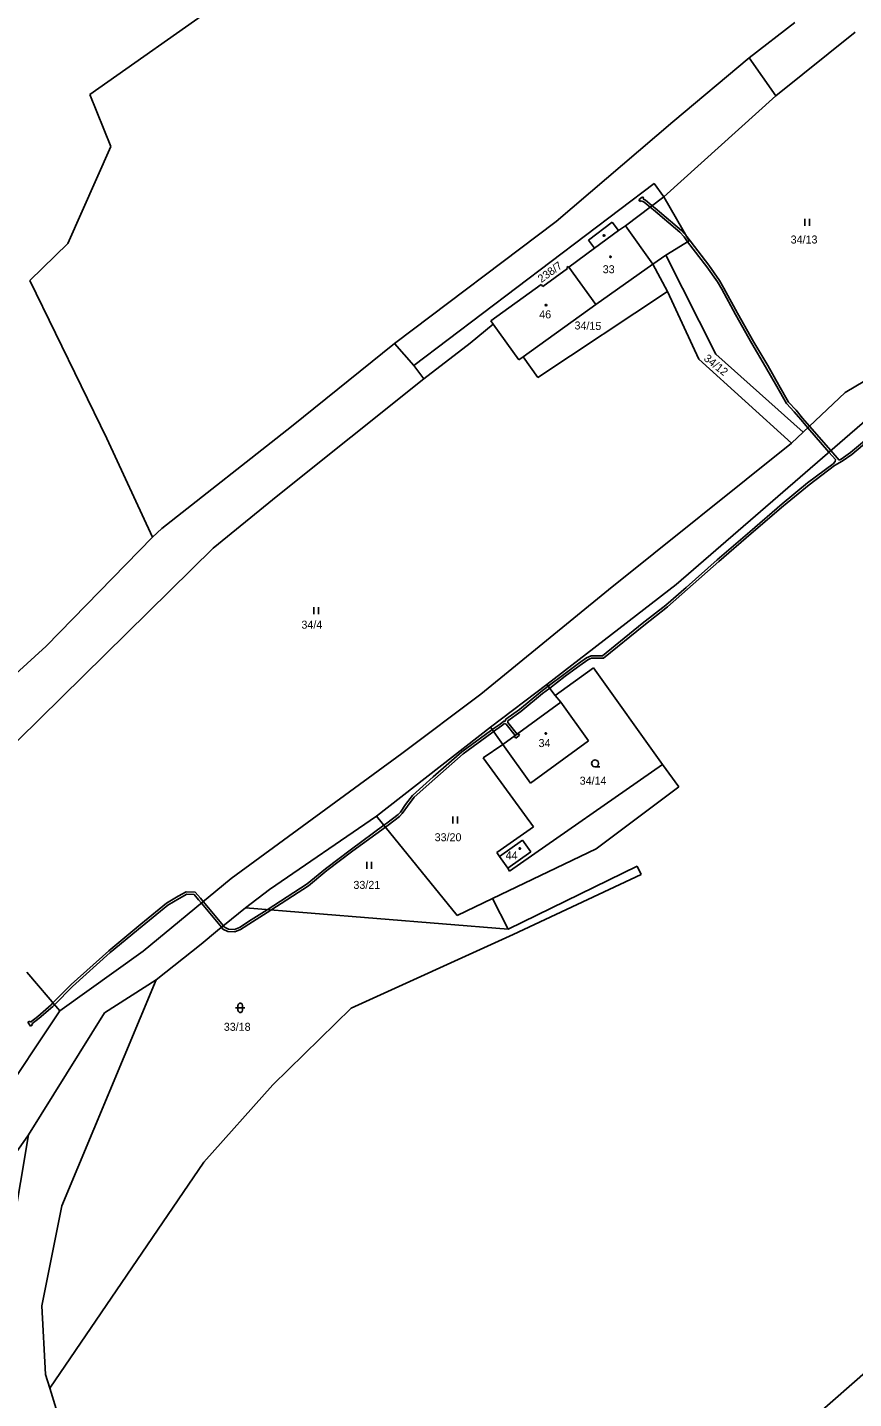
# Model space of a CAD drawing. Extents: x -811039 to -805820, y -1161436 to -1155864.
# Drawn here: x -810537.2 to -810361.7, y -1161047.6 to -1160756.4 of the extents above; entities that cross this region are included whole.
import ezdxf

# ---------------------------------------------------------------- set-up
doc = ezdxf.new("R2010")
doc.units = 0
for name, color, linetype in [('Default', 7, 'Continuous'), ('Hranice parcel', 7, 'Continuous'), ('Parcelní čísla', 7, 'Continuous'), ('Vnitřní kresba', 7, 'Continuous'), ('Věcná břemena k části', 7, 'Continuous'), ('Značky budov', 7, 'Continuous'), ('Značky kultur', 7, 'Continuous')]:
    doc.layers.add(name, color=color, linetype=linetype)

# ---------------------------------------------------------------- blocks, each defined once
blk = doc.blocks.new('304')
at = {"layer": 'Default'}
blk.add_lwpolyline([(0, 0), (-0.38, 0.1), (-0.65, 0.37), (-0.75, 0.74), (-0.65, 1.11), (-0.38, 1.38), (-0.01, 1.48), (0.36, 1.38), (0.63, 1.11), (0.73, 0.73), (0.63, 0.35), (0.36, 0.08), (-0.02, -0.02), (0.98, -0.02)], dxfattribs=at)
blk = doc.blocks.new('306')
at = {"layer": 'Default'}
for p, q in [((-0.5, 1.5), (-0.5, 0)), ((0.5, 0), (0.5, 1.5))]:
    blk.add_line(p, q, dxfattribs=at)
blk = doc.blocks.new('316')
at = {"layer": 'Default'}
for points in [[(-1, 1), (0.27, 1), (1, 1)], [(-0.5, 1.5), (-0.4, 1.79), (-0.15, 1.97), (0.16, 1.97), (0.41, 1.79), (0.51, 1.5), (0.51, 0.5), (0.41, 0.21), (0.16, 0.03), (-0.15, 0.03), (-0.4, 0.21), (-0.5, 0.5), (-0.5, 1.5)]]:
    blk.add_lwpolyline(points, dxfattribs=at)
blk = doc.blocks.new('402')
at = {"layer": 'Default'}
blk.add_lwpolyline([(0.09, 0.15), (0.18, 0), (0.09, -0.15), (-0.09, -0.15), (-0.18, 0), (-0.09, 0.15), (0.09, 0.15)], dxfattribs=at)

msp = doc.modelspace()

# ---------------------------------------------------------------- linework, layer by layer
at = {"layer": 'Hranice parcel'}
for p, q in [((-810495.95, -1160750.93), (-810523.97, -1160770.58)), ((-810383.89, -1160762.81), (-810374.25, -1160755.33)), ((-810361.37, -1160757.38), (-810378.26, -1160770.87)), ((-810400.09, -1160776.41), (-810383.89, -1160762.81)), ((-810523.97, -1160770.58), (-810519.48, -1160781.67)), ((-810378.26, -1160770.87), (-810402.06, -1160792.32)), ((-810400.09, -1160776.41), (-810424.9, -1160797.56)), ((-810519.48, -1160781.67), (-810528.63, -1160802.23)), ((-810404.12, -1160789.52), (-810455.16, -1160828.19)), ((-810402.06, -1160792.32), (-810404.12, -1160789.52)), ((-810402.06, -1160792.32), (-810410.16, -1160798.46)), ((-810402.06, -1160792.32), (-810396.64, -1160801.67)), ((-810424.9, -1160797.56), (-810459.25, -1160823.48)), ((-810413.01, -1160797.73), (-810418.01, -1160801.55)), ((-810411.63, -1160799.49), (-810413.01, -1160797.73)), ((-810410.16, -1160798.46), (-810411.63, -1160799.49)), ((-810528.63, -1160802.23), (-810536.67, -1160810.12)), ((-810416.75, -1160803.27), (-810422.24, -1160807.27)), ((-810418.01, -1160801.55), (-810416.75, -1160803.27)), ((-810396.64, -1160801.67), (-810401.59, -1160804.69)), ((-810401.59, -1160804.69), (-810404.35, -1160806.62)), ((-810401.59, -1160804.69), (-810391.01, -1160825.74)), ((-810422.5, -1160807.55), (-810427.75, -1160811.4)), ((-810422.35, -1160807.12), (-810422.66, -1160807.34)), ((-810422.5, -1160807.55), (-810422.66, -1160807.34)), ((-810422.24, -1160807.27), (-810422.35, -1160807.12)), ((-810422.24, -1160807.27), (-810416.48, -1160815.21)), ((-810416.48, -1160815.21), (-810404.35, -1160806.62)), ((-810404.35, -1160806.62), (-810401.26, -1160812.41)), ((-810536.67, -1160810.12), (-810520.32, -1160843.66)), ((-810428.1, -1160810.94), (-810438.78, -1160818.67)), ((-810428.1, -1160810.94), (-810427.75, -1160811.4)), ((-810428.81, -1160830.74), (-810401.26, -1160812.41)), ((-810401.26, -1160812.41), (-810394.63, -1160826.8)), ((-810416.48, -1160815.21), (-810431.93, -1160826.31)), ((-810363.54, -1160833.87), (-810331.75, -1160815.16)), ((-810438.26, -1160819.39), (-810443.14, -1160823.4)), ((-810438.78, -1160818.67), (-810438.26, -1160819.39)), ((-810438.26, -1160819.39), (-810432.81, -1160826.94)), ((-810459.25, -1160823.48), (-810481.1, -1160841.14)), ((-810443.14, -1160823.4), (-810453.03, -1160830.99)), ((-810432.81, -1160826.94), (-810431.93, -1160826.31)), ((-810428.81, -1160830.74), (-810431.93, -1160826.31)), ((-810391.01, -1160825.74), (-810372.47, -1160842.32)), ((-810455.16, -1160828.19), (-810453.03, -1160830.99)), ((-810394.63, -1160826.8), (-810374.94, -1160844.63)), ((-810453.03, -1160830.99), (-810484, -1160855.74)), ((-810372.47, -1160842.32), (-810363.54, -1160833.87)), ((-810399.4, -1160874.7), (-810354.5, -1160835.77)), ((-810508.66, -1160862.79), (-810481.1, -1160841.14)), ((-810520.32, -1160843.66), (-810510.6, -1160864.59)), ((-810374.94, -1160844.63), (-810372.47, -1160842.32)), ((-810413.8, -1160875.77), (-810374.94, -1160844.63)), ((-810484, -1160855.74), (-810497.78, -1160866.95)), ((-810510.6, -1160864.59), (-810508.66, -1160862.79)), ((-810497.78, -1160866.95), (-810545.34, -1160913.8)), ((-810510.6, -1160864.59), (-810533.18, -1160887.75)), ((-810440.91, -1160897.93), (-810413.8, -1160875.77)), ((-810426.88, -1160895.88), (-810399.4, -1160874.7)), ((-810533.18, -1160887.75), (-810595.17, -1160944.17)), ((-810417, -1160892.37), (-810425.11, -1160898.24)), ((-810402.3, -1160912.87), (-810417, -1160892.37)), ((-810438.86, -1160904.96), (-810426.88, -1160895.88)), ((-810425.11, -1160898.24), (-810426.88, -1160895.88)), ((-810457.71, -1160910.59), (-810440.91, -1160897.93)), ((-810425.11, -1160898.24), (-810423.94, -1160899.66)), ((-810423.94, -1160899.66), (-810418.05, -1160907.88)), ((-810463.04, -1160923.9), (-810438.86, -1160904.96)), ((-810438.86, -1160904.96), (-810436.22, -1160908.66)), ((-810418.05, -1160907.88), (-810430.37, -1160916.87)), ((-810493.91, -1160937.11), (-810457.71, -1160910.59)), ((-810436.22, -1160908.66), (-810440.39, -1160911.48)), ((-810430.37, -1160916.87), (-810436.22, -1160908.66)), ((-810440.39, -1160911.48), (-810429.7, -1160926.15)), ((-810434.81, -1160935.56), (-810402.3, -1160912.87)), ((-810402.3, -1160912.87), (-810398.85, -1160917.65)), ((-810398.85, -1160917.65), (-810416.39, -1160930.82)), ((-810463.04, -1160923.9), (-810485.8, -1160939.44)), ((-810445.93, -1160944.94), (-810463.04, -1160923.9)), ((-810429.7, -1160926.15), (-810437.53, -1160931.57)), ((-810438.42, -1160941.35), (-810416.39, -1160930.82)), ((-810436.91, -1160932.46), (-810432.02, -1160928.98)), ((-810430.29, -1160931.42), (-810435.18, -1160934.91)), ((-810432.02, -1160928.98), (-810430.29, -1160931.42)), ((-810437.53, -1160931.57), (-810436.91, -1160932.46)), ((-810435.18, -1160934.91), (-810436.91, -1160932.46)), ((-810512.63, -1160952.57), (-810493.91, -1160937.11)), ((-810435.18, -1160934.91), (-810434.81, -1160935.56)), ((-810407.69, -1160934.51), (-810435.08, -1160947.9)), ((-810406.87, -1160936.24), (-810434.06, -1160948.99)), ((-810407.69, -1160934.51), (-810406.87, -1160936.24)), ((-810485.8, -1160939.44), (-810490.9, -1160943.37)), ((-810445.93, -1160944.94), (-810438.42, -1160941.35)), ((-810435.08, -1160947.9), (-810438.42, -1160941.35)), ((-810490.9, -1160943.37), (-810496.84, -1160948.18)), ((-810435.08, -1160947.9), (-810490.9, -1160943.37)), ((-810496.84, -1160948.18), (-810500.32, -1160951.09)), ((-810500.32, -1160951.09), (-810509.82, -1160958.61)), ((-810434.06, -1160948.99), (-810468.42, -1160964.68)), ((-810530.31, -1160965.25), (-810512.63, -1160952.57)), ((-810530.31, -1160965.25), (-810537.29, -1160957)), ((-810529.92, -1161006.64), (-810509.82, -1160958.61)), ((-810509.82, -1160958.61), (-810520.81, -1160965.65)), ((-810549.36, -1160993.72), (-810530.31, -1160965.25)), ((-810520.81, -1160965.65), (-810536.99, -1160991.57)), ((-810485.1, -1160980.96), (-810468.42, -1160964.68)), ((-810499.76, -1160997.38), (-810485.1, -1160980.96)), ((-810536.99, -1160991.57), (-810560.62, -1161025.39)), ((-810536.99, -1160991.57), (-810544.89, -1161038.54)), ((-810499.76, -1160997.38), (-810532.44, -1161045.37)), ((-810534.14, -1161027.86), (-810529.92, -1161006.64)), ((-810533.34, -1161042.48), (-810534.14, -1161027.86)), ((-810376.47, -1161057.05), (-810353.34, -1161036.78)), ((-810533.34, -1161042.48), (-810532.44, -1161045.37)), ((-810532.44, -1161045.37), (-810531.08, -1161049.77))]:
    msp.add_line(p, q, dxfattribs=at)
at = {"layer": 'Vnitřní kresba'}
for p, q in [((-810416.75, -1160803.27), (-810411.63, -1160799.49)), ((-810404.35, -1160806.62), (-810410.16, -1160798.46)), ((-810436.22, -1160908.66), (-810423.94, -1160899.66))]:
    msp.add_line(p, q, dxfattribs=at)
at = {"layer": 'Věcná břemena k části'}
for p, q in [((-810407.34, -1160792.94), (-810406.57, -1160792.31)), ((-810407.03, -1160793.33), (-810407.34, -1160792.94)), ((-810406.86, -1160793.19), (-810407.03, -1160793.33)), ((-810406.22, -1160793.46), (-810406.86, -1160793.19)), ((-810406.57, -1160792.31), (-810406.25, -1160792.7)), ((-810406.25, -1160792.7), (-810406.42, -1160792.83)), ((-810406.42, -1160792.83), (-810405.96, -1160793.04)), ((-810404.96, -1160794.52), (-810406.22, -1160793.46)), ((-810405.96, -1160793.04), (-810404.55, -1160794.21)), ((-810404.22, -1160795.13), (-810404.96, -1160794.52)), ((-810404.55, -1160794.21), (-810403.9, -1160794.75)), ((-810398.66, -1160799.87), (-810404.22, -1160795.13)), ((-810403.9, -1160794.75), (-810398.32, -1160799.51)), ((-810397.75, -1160800.86), (-810398.66, -1160799.87)), ((-810398.32, -1160799.51), (-810397.17, -1160800.75)), ((-810396.98, -1160801.87), (-810397.75, -1160800.86)), ((-810397.17, -1160800.75), (-810392.51, -1160806.88)), ((-810392.91, -1160807.18), (-810396.98, -1160801.87)), ((-810390.66, -1160810.37), (-810392.91, -1160807.18)), ((-810392.51, -1160806.88), (-810390.24, -1160810.09)), ((-810389.7, -1160811.94), (-810390.66, -1160810.37)), ((-810390.24, -1160810.09), (-810389.26, -1160811.7)), ((-810386.8, -1160817.31), (-810389.7, -1160811.94)), ((-810389.26, -1160811.7), (-810386.36, -1160817.07)), ((-810383.37, -1160823.49), (-810386.8, -1160817.31)), ((-810386.36, -1160817.07), (-810382.93, -1160823.23)), ((-810380.42, -1160828.41), (-810383.37, -1160823.49)), ((-810382.93, -1160823.23), (-810379.98, -1160828.15)), ((-810378.04, -1160832.59), (-810380.42, -1160828.41)), ((-810379.98, -1160828.15), (-810377.6, -1160832.35)), ((-810377.6, -1160832.35), (-810375.58, -1160835.96)), ((-810375.98, -1160836.26), (-810378.04, -1160832.59)), ((-810374.34, -1160837.98), (-810375.98, -1160836.26)), ((-810375.58, -1160835.96), (-810373.96, -1160837.64)), ((-810372.96, -1160839.65), (-810374.34, -1160837.98)), ((-810373.96, -1160837.64), (-810372.58, -1160839.33)), ((-810371.47, -1160841.37), (-810372.96, -1160839.65)), ((-810372.58, -1160839.33), (-810371.1, -1160841.03)), ((-810371.1, -1160841.03), (-810371.47, -1160841.37)), ((-810371.47, -1160841.37), (-810371.1, -1160841.03)), ((-810371.1, -1160841.03), (-810366.58, -1160846.24)), ((-810366.96, -1160846.57), (-810371.47, -1160841.37)), ((-810362.41, -1160846.66), (-810356.12, -1160841.37)), ((-810355.8, -1160841.75), (-810362.11, -1160847.06)), ((-810366.96, -1160846.57), (-810366.58, -1160846.24)), ((-810366.58, -1160846.24), (-810366.96, -1160846.57)), ((-810365.6, -1160848.13), (-810366.96, -1160846.57)), ((-810366.58, -1160846.24), (-810364.81, -1160848.27)), ((-810364.39, -1160848.03), (-810362.41, -1160846.66)), ((-810371.49, -1160853.07), (-810366.09, -1160849.03)), ((-810365.78, -1160849.42), (-810371.19, -1160853.47)), ((-810366.09, -1160849.03), (-810365.68, -1160848.56)), ((-810364.13, -1160848.45), (-810365.78, -1160849.42)), ((-810365.68, -1160848.56), (-810365.6, -1160848.13)), ((-810364.81, -1160848.27), (-810364.39, -1160848.03)), ((-810362.11, -1160847.06), (-810364.13, -1160848.45)), ((-810376.91, -1160857.56), (-810371.49, -1160853.07)), ((-810371.19, -1160853.47), (-810376.59, -1160857.94)), ((-810383.78, -1160863.45), (-810376.91, -1160857.56)), ((-810376.59, -1160857.94), (-810383.46, -1160863.83)), ((-810390.7, -1160869.43), (-810383.78, -1160863.45)), ((-810383.46, -1160863.83), (-810390.38, -1160869.81)), ((-810397.32, -1160875.28), (-810390.7, -1160869.43)), ((-810390.38, -1160869.81), (-810396.98, -1160875.66)), ((-810401.59, -1160879.03), (-810397.32, -1160875.28)), ((-810396.98, -1160875.66), (-810401.27, -1160879.41)), ((-810406.61, -1160882.98), (-810401.59, -1160879.03)), ((-810401.27, -1160879.41), (-810406.29, -1160883.38)), ((-810415.05, -1160889.79), (-810406.61, -1160882.98)), ((-810406.29, -1160883.38), (-810414.87, -1160890.29)), ((-810420.16, -1160891.47), (-810418.45, -1160890.28)), ((-810418.19, -1160890.7), (-810419.86, -1160891.87)), ((-810418.45, -1160890.28), (-810417.97, -1160890)), ((-810417.77, -1160890.46), (-810418.19, -1160890.7)), ((-810417.97, -1160890), (-810417.45, -1160889.82)), ((-810417.37, -1160890.32), (-810417.77, -1160890.46)), ((-810417.45, -1160889.82), (-810415.05, -1160889.79)), ((-810414.87, -1160890.29), (-810417.37, -1160890.32)), ((-810423.29, -1160893.77), (-810420.16, -1160891.47)), ((-810419.86, -1160891.87), (-810422.99, -1160894.17)), ((-810428.13, -1160897.45), (-810426.58, -1160896.28)), ((-810426.58, -1160896.28), (-810423.29, -1160893.77)), ((-810426.58, -1160896.28), (-810426.28, -1160896.68)), ((-810426.28, -1160896.68), (-810426.58, -1160896.28)), ((-810422.99, -1160894.17), (-810426.28, -1160896.68)), ((-810432.7, -1160901.24), (-810428.13, -1160897.45)), ((-810427.81, -1160897.85), (-810432.4, -1160901.64)), ((-810426.28, -1160896.68), (-810427.81, -1160897.85)), ((-810435.6, -1160903.3), (-810432.7, -1160901.24)), ((-810432.4, -1160901.64), (-810435.16, -1160903.6)), ((-810438.49, -1160905.48), (-810436.83, -1160904.3)), ((-810436.53, -1160904.7), (-810438.2, -1160905.89)), ((-810436.83, -1160904.3), (-810436.03, -1160903.71)), ((-810435.87, -1160904.21), (-810436.53, -1160904.7)), ((-810436.03, -1160903.71), (-810435.72, -1160903.72)), ((-810435.55, -1160904.32), (-810435.87, -1160904.21)), ((-810435.72, -1160903.72), (-810435.6, -1160903.3)), ((-810433.59, -1160906.73), (-810435.55, -1160904.32)), ((-810435.16, -1160903.6), (-810435.16, -1160904.01)), ((-810435.16, -1160904.01), (-810433.19, -1160906.44)), ((-810444.95, -1160910.24), (-810438.85, -1160905.74)), ((-810438.55, -1160906.14), (-810444.63, -1160910.64)), ((-810438.85, -1160905.74), (-810438.49, -1160905.48)), ((-810438.2, -1160905.89), (-810438.55, -1160906.14)), ((-810433.79, -1160906.88), (-810433.59, -1160906.73)), ((-810433.5, -1160907.28), (-810433.79, -1160906.88)), ((-810432.69, -1160906.69), (-810433.5, -1160907.28)), ((-810433.19, -1160906.44), (-810432.98, -1160906.29)), ((-810432.98, -1160906.29), (-810432.69, -1160906.69)), ((-810451.04, -1160915.54), (-810444.95, -1160910.24)), ((-810444.63, -1160910.64), (-810450.7, -1160915.92)), ((-810455.43, -1160919.51), (-810451.04, -1160915.54)), ((-810450.7, -1160915.92), (-810455.05, -1160919.85)), ((-810456.87, -1160921.42), (-810455.43, -1160919.51)), ((-810455.05, -1160919.85), (-810456.47, -1160921.72)), ((-810457.99, -1160923.02), (-810456.87, -1160921.42)), ((-810456.47, -1160921.72), (-810457.59, -1160923.34)), ((-810461.47, -1160925.82), (-810460.85, -1160925.37)), ((-810460.85, -1160925.37), (-810458.48, -1160923.55)), ((-810458.14, -1160923.93), (-810460.55, -1160925.77)), ((-810458.48, -1160923.55), (-810457.99, -1160923.02)), ((-810457.59, -1160923.34), (-810458.14, -1160923.93)), ((-810468.38, -1160930.85), (-810461.47, -1160925.82)), ((-810461.16, -1160926.21), (-810468.08, -1160931.25)), ((-810461.47, -1160925.82), (-810461.16, -1160926.21)), ((-810461.16, -1160926.21), (-810461.47, -1160925.82)), ((-810460.55, -1160925.77), (-810461.16, -1160926.21)), ((-810473.92, -1160935.03), (-810468.38, -1160930.85)), ((-810468.08, -1160931.25), (-810473.6, -1160935.43)), ((-810477.8, -1160938.25), (-810473.92, -1160935.03)), ((-810473.6, -1160935.43), (-810477.5, -1160938.65)), ((-810505.2, -1160940.89), (-810503.49, -1160939.94)), ((-810503.49, -1160939.94), (-810501.55, -1160940.04)), ((-810501.55, -1160940.04), (-810500.47, -1160941.29)), ((-810486.29, -1160943.74), (-810477.8, -1160938.25)), ((-810477.5, -1160938.65), (-810485.47, -1160943.81)), ((-810513.14, -1160946.83), (-810507.66, -1160942.37)), ((-810507.38, -1160942.79), (-810512.82, -1160947.21)), ((-810507.66, -1160942.37), (-810505.2, -1160940.89)), ((-810504.94, -1160941.33), (-810507.38, -1160942.79)), ((-810503.37, -1160940.44), (-810504.94, -1160941.33)), ((-810501.79, -1160940.52), (-810503.37, -1160940.44)), ((-810500.85, -1160941.61), (-810501.79, -1160940.52)), ((-810500.24, -1160942.34), (-810500.85, -1160941.61)), ((-810500.47, -1160941.29), (-810499.86, -1160942.02)), ((-810499.86, -1160942.02), (-810500.24, -1160942.34)), ((-810500.24, -1160942.34), (-810499.86, -1160942.02)), ((-810495.97, -1160947.47), (-810500.24, -1160942.34)), ((-810499.86, -1160942.02), (-810495.58, -1160947.16)), ((-810492.13, -1160947.51), (-810489.65, -1160945.92)), ((-810489.65, -1160945.92), (-810486.29, -1160943.74)), ((-810485.47, -1160943.81), (-810489.37, -1160946.34)), ((-810519.93, -1160952.48), (-810513.14, -1160946.83)), ((-810512.82, -1160947.21), (-810519.61, -1160952.86)), ((-810495.97, -1160947.47), (-810495.58, -1160947.16)), ((-810495.58, -1160947.16), (-810495.97, -1160947.47)), ((-810495.66, -1160947.84), (-810495.97, -1160947.47)), ((-810494.65, -1160948.34), (-810495.66, -1160947.84)), ((-810495.58, -1160947.16), (-810495.34, -1160947.44)), ((-810495.34, -1160947.44), (-810494.51, -1160947.84)), ((-810493.17, -1160948.43), (-810494.65, -1160948.34)), ((-810494.51, -1160947.84), (-810493.25, -1160947.93)), ((-810493.25, -1160947.93), (-810492.13, -1160947.51)), ((-810491.91, -1160947.97), (-810493.17, -1160948.43)), ((-810489.37, -1160946.34), (-810491.91, -1160947.97)), ((-810527.94, -1160959.66), (-810519.93, -1160952.48)), ((-810519.61, -1160952.86), (-810527.6, -1160960.02)), ((-810531.77, -1160963.52), (-810527.94, -1160959.66)), ((-810527.6, -1160960.02), (-810531.45, -1160963.91)), ((-810532.17, -1160963.93), (-810531.77, -1160963.52)), ((-810531.77, -1160963.52), (-810531.45, -1160963.91)), ((-810531.45, -1160963.91), (-810531.77, -1160963.52)), ((-810536.54, -1160967.6), (-810535, -1160966.4)), ((-810535, -1160966.4), (-810532.17, -1160963.93)), ((-810531.83, -1160964.29), (-810534.68, -1160966.78)), ((-810531.45, -1160963.91), (-810531.83, -1160964.29)), ((-810537.1, -1160967.66), (-810536.68, -1160967.39)), ((-810536.55, -1160968.5), (-810537.1, -1160967.66)), ((-810536.68, -1160967.39), (-810536.54, -1160967.6)), ((-810536.13, -1160968.22), (-810536.55, -1160968.5)), ((-810534.68, -1160966.78), (-810536.27, -1160968.01)), ((-810536.27, -1160968.01), (-810536.13, -1160968.22))]:
    msp.add_line(p, q, dxfattribs=at)
msp.add_lwpolyline([(-810455.16, -1160828.19), (-810459.25, -1160823.48), (-810424.9, -1160797.56), (-810400.09, -1160776.41), (-810383.89, -1160762.81), (-810378.26, -1160770.87), (-810402.06, -1160792.32), (-810404.12, -1160789.52)], close=True, dxfattribs=at)
for points in [[(-810397.17, -1160800.75), (-810396.64, -1160801.67), (-810396.98, -1160801.87)], [(-810396.98, -1160801.87), (-810396.64, -1160801.67), (-810397.17, -1160800.75)]]:
    msp.add_lwpolyline(points, dxfattribs=at)

# ---------------------------------------------------------------- block references
at = {"layer": 'Značky budov'}
for p in [(-810414.73, -1160800.55), (-810413.35, -1160805.06), (-810427.06, -1160815.33), (-810427.1, -1160906.3), (-810432.61, -1160930.74)]:
    msp.add_blockref('402', p, dxfattribs=at)
at = {"layer": 'Značky kultur'}
for name, p in [('306', (-810371.6, -1160798.52)), ('306', (-810475.88, -1160880.96)), ('304', (-810416.64, -1160913.4)), ('306', (-810446.37, -1160925.42)), ('306', (-810464.59, -1160935.04)), ('316', (-810492, -1160965.59))]:
    msp.add_blockref(name, p, dxfattribs=at)

# ---------------------------------------------------------------- texts
at = {"layer": 'Parcelní čísla'}
for s, p in [('34/13', (-810375.1, -1160802.25)), ('33', (-810415.01, -1160808.56)), ('46', (-810428.5, -1160818.15)), ('34/4', (-810479, -1160884.05)), ('34', (-810428.64, -1160909.2)), ('34/14', (-810419.91, -1160917.19)), ('33/20', (-810450.71, -1160929.2)), ('44', (-810435.64, -1160933.04)), ('33/21', (-810467.96, -1160939.32)), ('33/18', (-810495.49, -1160969.46))]:
    msp.add_text(s, height=1.7, dxfattribs=at).set_placement(p)
for s, rotation, p in [('238/7', 35.982, (-810428.04, -1160810.66)), ('34/15', 358.672, (-810421.02, -1160820.49)), ('34/12', 321.2, (-810393.7, -1160826.92))]:
    msp.add_text(s, height=1.7, rotation=rotation, dxfattribs=at).set_placement(p)

doc.saveas('drawing.dxf')
